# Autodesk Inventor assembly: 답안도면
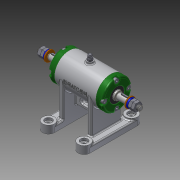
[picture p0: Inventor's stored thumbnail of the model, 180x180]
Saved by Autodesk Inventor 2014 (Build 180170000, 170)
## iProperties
Created: 2015-11
Part Number: 답안도면
Document SubType Name: Assembly
Designer: 702
Author: 702
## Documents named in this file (16)
- C:\Users\702\Desktop\451109V1010\답안도면.iam
- C:\Users\702\Desktop\451109V1010\본체.ipt
- C:\Users\702\Desktop\451109V1010\V벨트풀리.ipt
- C:\Users\702\Desktop\451109V1010\너트 M 8.ipt
- C:\Users\702\Desktop\451109V1010\니플 M 6 x 0.75.ipt
- C:\Users\702\Desktop\451109V1010\베어링 15 x 32 x 9.ipt
- C:\Users\702\Desktop\451109V1010\볼트 M 6 x 8.ipt
- C:\Users\702\Desktop\451109V1010\볼트 M4 x 12.ipt
- C:\Users\702\Desktop\451109V1010\스퍼기어.ipt
- C:\Users\702\Desktop\451109V1010\스프링와셔 8.ipt
- C:\Users\702\Desktop\451109V1010\오일 실 15 25 7.ipt
- C:\Users\702\Desktop\451109V1010\와셔 6x11.5.ipt
- C:\Users\702\Desktop\451109V1010\와셔 8x17.ipt
- C:\Users\702\Desktop\451109V1010\축.ipt
- C:\Users\702\Desktop\451109V1010\커버.ipt
- C:\Users\702\Desktop\451109V1010\키 3 x 3 x 12.ipt
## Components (8 placed, 3 different names)
1. V벨트풀리:1
2. KS B 2023 6002 - 15 x 32 x 9:1
3. ISO 4762 M4 x 12:1
4. KS B 2023 6002 - 15 x 32 x 9:2
5. ISO 4762 M4 x 12:2
6. ISO 4762 M4 x 12:3
7. ISO 4762 M4 x 12:4
8. ISO 4762 M4 x 12:5
